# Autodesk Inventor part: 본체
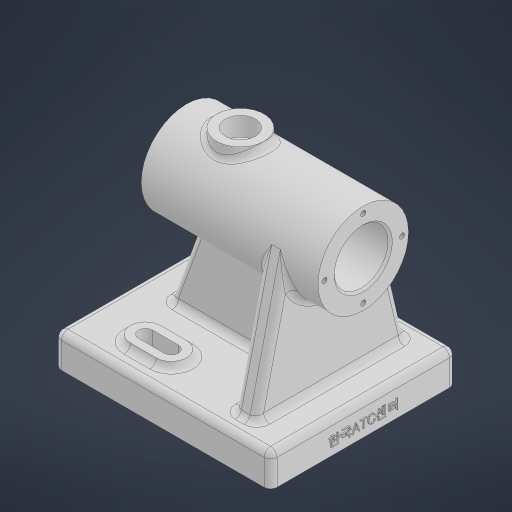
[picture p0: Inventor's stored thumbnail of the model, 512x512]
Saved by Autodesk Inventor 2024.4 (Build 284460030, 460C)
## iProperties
Created: 2026-09
Part Number: 본체
Material: 일반
Document SubType Name: Modeling
Designer: user
Density: 1 g/cm^3
Appearance: 기본값
Author: user
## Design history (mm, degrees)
sketch "스케치1"
  geometry: L1 (-41, 0)-(41, 0); L2 (-41, 21)-(41, 21); L3 (41, 21)-(41, 12.5); L4 (41, 12.5)-(21, 12.5); L5 (21, 12.5)-(21, 14.5); L6 (21, 14.5)-(-41, 14.5); L7 (-41, 14.5)-(-41, 21); L8 (-59, -57)-(41, -57); L9 (41, -57)-(41, -72); L10 (41, -72)-(-59, -72); L11 (-59, -72)-(-59, -57); 2 further points
  constraints: 22 end point, 5 perpendicular, 3 horizontal, 3 parallel, 3 point on line, 1 coincident, 1 midpoint
  dimensions: "d0" = 82 distance of L1.start L1.end; "d1" = 42 diameter of L2 L1; "d2" = 29 diameter of L6 L1; "d3" = 25 diameter of L4 L1; "d4" = 62 distance between parallel lines of L5 L7; "d5" = 100 distance between parallel lines of L9 L11; "d6" = 144 diameter of L10 L1; "d7" = 15 distance between parallel lines of L8 L10
revolve "회전1" stored, may be unused: angle "d8" = 90 deg
extrude "돌출1" join sketch "스케치1" stored distance "d9" = 86; taper "d10" = 0 deg
node "작업 평면1"
sketch "스케치3"
  geometry: L1 (86, 15)-(0, 15) reference; L2 (0, 15)-(0, 0) reference; L3 (86, 0)-(86, 15) reference; L4 (22.559, 76.814)-(8, 15); L5 (63.441, 76.814)-(78, 15); A1 r 21 centre (43, 72) between (22.559, 76.814) and (63.441, 76.814) reference; 1 further point
  constraints: 4 end point, 2 point on circle, 2 point on line, 2 tangent
  dimensions: "d18" = 8 distance of L4.end L1.end; "d19" = 8 distance of L1.start L5.end
extrude "돌출2" join sketch "스케치3" distance "d20" = 10; taper "d21" = 0 deg
sketch "스케치4"
  geometry: L1 (-59, -57)-(41, -57) reference; L2 (-44, -57)-(-30.897, -21); L3 (-41, -21)-(41, -21) reference; L4 (-59, -72)-(-59, -57) reference; 1 further point
  constraints: 2 end point, 2 point on line
  dimensions: "d22" = 15 distance from line of L2.start L4; "d23" = 70 deg angle of L1 L2
feature "리브1" sketch "스케치4" dims "d24" = 1, "d25" = 10, "d26" = 0, "d27" = 0, "d28" = 1, "d29" = 1
sketch "스케치5" dims "d37" = 36
  geometry: C1 r 21 at (0, 0) reference; 3 further points
  constraints: 2 vertical alignment, 1 coincident, 2 other
hole "구멍1" sketch "스케치5" at (0, 18) diameter "d30" = 2.459; stored, may be unused: countersink angle "d34" = 90 deg, drill point angle "d36" = 118 deg; dims "d31" = 8, "d32" = 4, "d33" = 2, "d35" = 10
node "작업 평면2"
chamfer "모따기1" distance "d41" = 1; stored, may be unused: second distance "d42" = 2, angle "d43" = 45 deg
sketch "스케치6"
  geometry: L1 (0, 0)-(100, 0) reference; L2 (0, 0)-(0, -86) reference; L3 (26, -16)-(38, -16); L4 (26, -23)-(38, -23); L5 (38, -9)-(26, -9); L6 (26, -70)-(38, -70); L7 (26, -77)-(38, -77); L8 (38, -63)-(26, -63); A1 r 7 centre (26, -16) between (26, -9) and (26, -23); A2 r 7 centre (38, -16) between (38, -23) and (38, -9); A3 r 7 centre (26, -70) between (26, -63) and (26, -77); A4 r 7 centre (38, -70) between (38, -77) and (38, -63); 3 further points
  constraints: 16 end point, 8 point on circle, 8 tangent, 4 centre point, 3 parallel, 2 midpoint, 1 horizontal, 1 vertical alignment
  dimensions: "d44" = 12 distance of L6.end L6.start; "d45" = 12 distance of L3.end L3.start; "d46" = 54 distance of point (32, -16) point (32, -70); "d47" = 26 distance from line of L6.start L2; "d48" = 16 distance from line of L1 point (32, -16); "d52" = 14 distance between parallel lines of L5 L4; "d53" = 14 distance between parallel lines of L8 L7
extrude "돌출3" join sketch "스케치6" distance "d49" = 3; taper "d50" = 0 deg
sketch "스케치7"
  geometry: L1 (26, -77)-(38, -77) reference; L2 (26, -70)-(38, -70); L3 (26, -66.7)-(38, -66.7); L4 (38, -73.3)-(26, -73.3); A1 r 7 centre (38, -70) between (38, -77) and (38, -63) reference; A2 r 7 centre (26, -70) between (26, -63) and (26, -77) reference; A3 r 3.3 centre (26, -70) between (26, -66.7) and (26, -73.3); A4 r 3.3 centre (38, -70) between (38, -73.3) and (38, -66.7); 2 further points
  constraints: 8 end point, 4 point on circle, 4 tangent, 2 centre point, 2 parallel, 1 midpoint
  dimensions: "d51" = 6.6 distance between parallel lines of L3 L4
extrude "돌출4" cut sketch "스케치7" extent not by distance; stored distance "d54" = 0; taper "d55" = 0 deg
fillet "모깎기1" dims "d56" = 3
node "작업 평면3"
sketch "스케치8"
  geometry: L1 (15, -64)-(15, -22) reference; C1 r 11 at (40, -43); 1 further point
  constraints: 1 centre point
  dimensions: "d58" = 25 distance from line of C1.centre L1; "d59" = 22 diameter of C1
extrude "돌출5" join sketch "스케치8" stored distance "d60" = 10; taper "d61" = 0 deg
sketch "스케치9"
  geometry: C1 r 11 at (0, 0) reference; 2 further points
  constraints: 1 coincident
hole "구멍2" sketch "스케치9" at (0, 0) diameter "d62" = 4.917; stored, may be unused: countersink angle "d66" = 90 deg, drill point angle "d68" = 118 deg; dims "d63" = 12, "d64" = 14, "d65" = 8.75, "d67" = 17.1
fillet "모깎기2" dims "d69" = 3
fillet "모깎기3" dims "d70" = 3
fillet "모깎기4" dims "d71" = 3
fillet "모깎기5" dims "d72" = 3
fillet "모깎기6" dims "d73" = 3
sketch "스케치10"
  geometry: L1 (80, 0)-(0, 0) reference; 2 further points
  constraints: 1 vertical alignment, 1 other
  dimensions: "d74" = 6 distance from line of point (40, 6) L1
feature "엠보싱1" sketch "스케치10" dims "d75" = 0.5, "d76" = 0
fillet "모깎기7" dims "d77" = 3
node "솔리드1"
pattern_circular "원형 패턴1" dims angle "d39" = 360 deg
mirror "미러1"
mirror "미러2"
feature "A9D066F2-1C7D-4E18-AEED-F7BC21143FA4" dims "d30" = 2.459, "d31" = 8, "d32" = 4, "d33" = 2, "d34" = 90 deg, "d35" = 10, "d36" = 118 deg
other parameters: "d15" = -15, "d57" = -96
